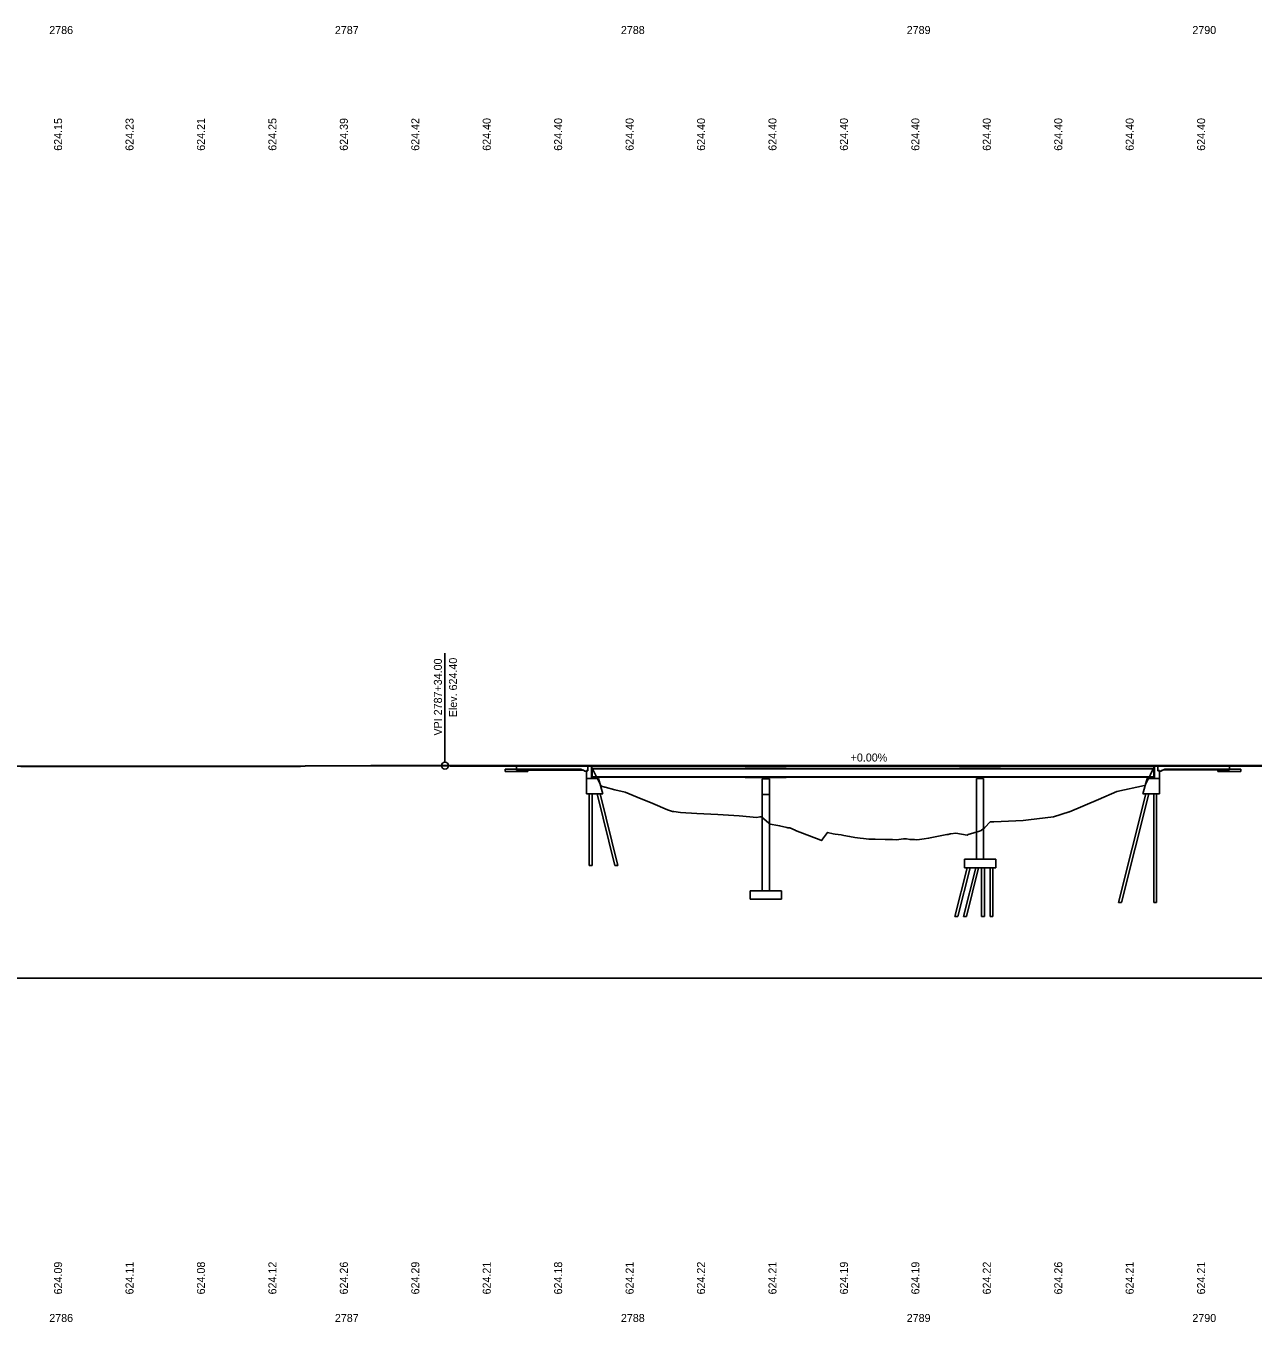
# Model space of a CAD drawing. Extents: x 2376379 to 2383101, y 559608 to 561720.
# Drawn here: x 2379153 to 2379582.4, y 559608.2 to 560061.6 of the extents above; entities that cross this region are included whole.
import ezdxf

# ---------------------------------------------------------------- set-up
doc = ezdxf.new("R2010")
doc.units = 0
for name, color, linetype in [('AP_P_Airside', 7, 'Continuous'), ('BR_X_SV_Abut', 7, 'Continuous'), ('BR_X_SV_Shot_Marker', 7, 'Continuous'), ('DR_X_Ditch', 7, 'Continuous'), ('DR_X_Erosion_Control', 7, 'Continuous'), ('DR_X_Storm_Sewer', 7, 'Continuous'), ('DR_X_Text', 7, 'Continuous'), ('DT_X_Terrain_Ground_Line', 7, 'Continuous'), ('PV_X_Driveway', 7, 'Continuous'), ('SC_Scratch1', 7, 'Continuous'), ('SV_X_Control_Cells_Found', 7, 'Continuous'), ('SV_X_Text', 7, 'Continuous'), ('UT_X_Overhead_Electric', 7, 'Continuous')]:
    doc.layers.add(name, color=color, linetype=linetype)

msp = doc.modelspace()

# ---------------------------------------------------------------- linework, layer by layer
at = {"layer": 'AP_P_Airside'}
msp.add_line((2379299.62, 559804.07), (2379299.62, 559842.15), dxfattribs=at)
msp.add_circle((2379299.62, 559802.86), 1.21, dxfattribs=at)
at = {"layer": 'BR_X_SV_Abut'}
for p, q in [((2379351.45, 559798.82), (2379351.45, 559798.57)), ((2379352.28, 559798.82), (2379351.45, 559798.82)), ((2379352.28, 559798.82), (2379352.28, 559798.57)), ((2379411.28, 559798.76), (2379411.28, 559798.55)), ((2379412.45, 559798.76), (2379411.28, 559798.76)), ((2379412.45, 559798.76), (2379412.45, 559798.55)), ((2379486.27, 559798.8), (2379486.27, 559798.67)), ((2379487.44, 559798.8), (2379486.27, 559798.8)), ((2379487.44, 559798.67), (2379486.27, 559798.67)), ((2379486.32, 559798.67), (2379486.32, 559798.38)), ((2379487.4, 559798.67), (2379487.4, 559798.38)), ((2379487.44, 559798.8), (2379487.44, 559798.67)), ((2379546.44, 559798.82), (2379546.44, 559798.57)), ((2379547.27, 559798.82), (2379546.44, 559798.82)), ((2379547.27, 559798.82), (2379547.27, 559798.57)), ((2379352.28, 559798.57), (2379351.45, 559798.57)), ((2379351.49, 559798.57), (2379351.49, 559798.34)), ((2379352.24, 559798.34), (2379351.49, 559798.34)), ((2379352.24, 559798.57), (2379352.24, 559798.34)), ((2379412.45, 559798.55), (2379411.28, 559798.55)), ((2379411.33, 559798.55), (2379411.33, 559798.26)), ((2379412.41, 559798.26), (2379411.33, 559798.26)), ((2379412.41, 559798.55), (2379412.41, 559798.26)), ((2379487.4, 559798.38), (2379486.32, 559798.38)), ((2379547.27, 559798.57), (2379546.44, 559798.57)), ((2379546.48, 559798.57), (2379546.48, 559798.34)), ((2379547.23, 559798.34), (2379546.48, 559798.34)), ((2379547.23, 559798.57), (2379547.23, 559798.34))]:
    msp.add_line(p, q, dxfattribs=at)
at = {"layer": 'DR_X_Ditch'}
for p, q in [((2379351.12, 559801.88), (2379351.12, 559798.88)), ((2379351.12, 559801.88), (2379547.62, 559801.88)), ((2379351.12, 559801.8), (2379547.62, 559801.8)), ((2379351.12, 559798.97), (2379547.62, 559798.97)), ((2379351.12, 559798.88), (2379547.62, 559798.88)), ((2379404.7, 559801.88), (2379404.7, 559801.92)), ((2379404.7, 559801.92), (2379419.03, 559801.92)), ((2379404.7, 559801.88), (2379404.7, 559801.92)), ((2379404.7, 559798.84), (2379404.7, 559798.88)), ((2379404.7, 559798.84), (2379419.03, 559798.84)), ((2379419.03, 559801.88), (2379419.03, 559801.92)), ((2379419.03, 559801.88), (2379419.03, 559801.92)), ((2379419.03, 559798.84), (2379419.03, 559798.88)), ((2379479.69, 559801.92), (2379494.02, 559801.92)), ((2379479.69, 559801.88), (2379479.69, 559801.92)), ((2379479.69, 559798.84), (2379479.69, 559798.88)), ((2379479.69, 559798.84), (2379494.02, 559798.84)), ((2379494.02, 559801.88), (2379494.02, 559801.92)), ((2379494.02, 559798.84), (2379494.02, 559798.88)), ((2379547.62, 559801.88), (2379547.62, 559798.88))]:
    msp.add_line(p, q, dxfattribs=at)
at = {"layer": 'DR_X_Storm_Sewer'}
for p, q in [((2379324.62, 559801.61), (2379324.62, 559802.86)), ((2379324.62, 559801.61), (2379347.2, 559801.61)), ((2379348.62, 559800.9), (2379347.2, 559801.61)), ((2379348.62, 559800.9), (2379349.12, 559800.9)), ((2379549.62, 559800.9), (2379550.11, 559800.9)), ((2379550.11, 559800.9), (2379551.53, 559801.61)), ((2379551.53, 559801.61), (2379574.12, 559801.61)), ((2379574.12, 559802.86), (2379574.12, 559801.61))]:
    msp.add_line(p, q, dxfattribs=at)
at = {"layer": 'DR_X_Text'}
for p, q in [((2379404.7, 559798.76), (2379404.7, 559798.8)), ((2379404.7, 559798.8), (2379419.03, 559798.8)), ((2379404.7, 559798.76), (2379419.03, 559798.76)), ((2379419.03, 559798.76), (2379419.03, 559798.8)), ((2379479.69, 559798.8), (2379479.69, 559798.84)), ((2379479.69, 559798.84), (2379494.02, 559798.84)), ((2379479.69, 559798.8), (2379494.02, 559798.8)), ((2379494.02, 559798.8), (2379494.02, 559798.84))]:
    msp.add_line(p, q, dxfattribs=at)
at = {"layer": 'DT_X_Terrain_Ground_Line'}
for p, q in [((2379320.62, 559800.86), (2379320.62, 559801.61)), ((2379324.62, 559801.61), (2379320.62, 559801.61)), ((2379320.62, 559800.86), (2379328.62, 559800.86)), ((2379328.62, 559800.86), (2379328.62, 559801.61)), ((2379570.12, 559801.61), (2379570.12, 559800.86)), ((2379570.12, 559800.86), (2379578.12, 559800.86)), ((2379574.12, 559801.61), (2379578.12, 559801.61)), ((2379578.12, 559801.61), (2379578.12, 559800.86))]:
    msp.add_line(p, q, dxfattribs=at)
at = {"layer": 'PV_X_Driveway'}
msp.add_lwpolyline([(2379151.22, 559802.54), (2379175.95, 559802.56), (2379192.51, 559802.57), (2379193.1, 559802.57), (2379198.76, 559802.57), (2379202.7, 559802.56), (2379223.33, 559802.53), (2379225.57, 559802.54), (2379247.27, 559802.61), (2379249.06, 559802.61), (2379250.63, 559802.62), (2379273.71, 559802.79), (2379297.46, 559802.74), (2379298.49, 559802.74), (2379301.44, 559802.73), (2379321.77, 559802.65), (2379322.73, 559802.64), (2379329.83, 559802.62), (2379330.86, 559802.62), (2379350.79, 559802.67), (2379354, 559796.11), (2379354.25, 559795.63), (2379354.29, 559795.64), (2379354.37, 559795.64), (2379355.61, 559795.32), (2379355.62, 559795.31), (2379359.07, 559794.38), (2379362.7, 559793.61), (2379366.85, 559791.86), (2379372.33, 559789.58), (2379377.43, 559787.42), (2379379.21, 559786.84), (2379379.32, 559786.83), (2379379.33, 559786.83), (2379379.71, 559786.77), (2379382.02, 559786.46), (2379387.77, 559786.13), (2379395.14, 559785.72), (2379402.54, 559785.34), (2379408.74, 559784.74), (2379409.78, 559784.94), (2379409.9, 559784.96), (2379410.33, 559784.93), (2379412.96, 559782.69), (2379413.38, 559782.38), (2379416.13, 559781.88), (2379416.73, 559781.81), (2379419.25, 559781.24), (2379419.58, 559781.16), (2379419.73, 559781.13), (2379420.33, 559781.07), (2379422.1, 559780.32), (2379422.23, 559780.19), (2379431.15, 559776.82), (2379431.47, 559776.63), (2379431.75, 559777.13), (2379433.44, 559779.51), (2379435.45, 559779.06), (2379436.21, 559778.94), (2379438.29, 559778.6), (2379439.21, 559778.44), (2379441.18, 559778.11), (2379443, 559777.74), (2379444.96, 559777.44), (2379446.03, 559777.34), (2379447.96, 559777.12), (2379449.07, 559777.12), (2379450.21, 559777.09), (2379453.66, 559777.02), (2379455.09, 559777.02), (2379456.23, 559777.03), (2379457.58, 559776.96), (2379460.08, 559777.23), (2379461.16, 559777.2), (2379462.36, 559776.99), (2379463.33, 559777), (2379463.95, 559776.97), (2379464.73, 559776.93), (2379465.63, 559776.99), (2379467.25, 559777.2), (2379468.86, 559777.47), (2379475.29, 559778.78), (2379475.72, 559778.82), (2379476.08, 559778.89), (2379476.4, 559778.99), (2379476.61, 559779.05), (2379478.38, 559779.19), (2379482.37, 559778.56), (2379482.75, 559778.75), (2379486.64, 559779.89), (2379487.25, 559780.18), (2379488.53, 559781.19), (2379490.34, 559783.2), (2379491.64, 559783.19), (2379501.98, 559783.71), (2379503.77, 559783.9), (2379512.59, 559784.9), (2379518.1, 559786.76), (2379518.12, 559786.76), (2379528.34, 559790.96), (2379534.7, 559793.78), (2379544.45, 559795.9), (2379544.55, 559795.93), (2379544.58, 559795.93), (2379544.61, 559795.99), (2379546.49, 559799.76), (2379547.93, 559802.66), (2379572.29, 559802.67), (2379573.41, 559802.67), (2379574.48, 559802.67), (2379598.49, 559802.67)], dxfattribs=at)
at = {"layer": 'SC_Scratch1'}
for p, q in [((2379349.12, 559798.34), (2379349.12, 559801.11)), ((2379349.12, 559801.11), (2379349.62, 559801.11)), ((2379349.62, 559801.11), (2379349.62, 559802.86)), ((2379350.87, 559798.34), (2379350.87, 559802.86)), ((2379547.87, 559798.34), (2379547.87, 559802.86)), ((2379549.12, 559801.11), (2379549.12, 559802.86)), ((2379549.12, 559801.11), (2379549.62, 559801.11)), ((2379549.62, 559798.34), (2379549.62, 559801.11)), ((2379350.87, 559798.34), (2379349.12, 559798.34)), ((2379547.87, 559798.34), (2379549.62, 559798.34))]:
    msp.add_line(p, q, dxfattribs=at)
at = {"layer": 'SV_X_Control_Cells_Found'}
for p, q in [((2379324.62, 559802.64), (2379324.62, 559801.3)), ((2379348.57, 559800.88), (2379348.12, 559801.33)), ((2379349.12, 559800.88), (2379348.57, 559800.88)), ((2379349.12, 559801.09), (2379349.12, 559792.95)), ((2379349.62, 559801.09), (2379349.12, 559801.09)), ((2379349.62, 559802.67), (2379349.62, 559801.09)), ((2379350.87, 559802.51), (2379350.87, 559798.34)), ((2379547.87, 559802.66), (2379547.87, 559798.34)), ((2379549.12, 559802.66), (2379549.12, 559801.08)), ((2379549.12, 559801.08), (2379549.62, 559801.08)), ((2379549.62, 559801.08), (2379549.62, 559792.95)), ((2379549.62, 559800.87), (2379550.12, 559800.87)), ((2379550.12, 559800.87), (2379550.58, 559801.33)), ((2379550.58, 559801.33), (2379574.12, 559801.34)), ((2379574.12, 559802.67), (2379574.12, 559801.34)), ((2379350.87, 559798.34), (2379353.37, 559798.34)), ((2379351.53, 559798.52), (2379351.53, 559798.34)), ((2379351.53, 559798.52), (2379352.2, 559798.52)), ((2379352.2, 559798.52), (2379352.2, 559798.34)), ((2379354.87, 559792.95), (2379353.37, 559798.34)), ((2379410.62, 559798.26), (2379410.62, 559759.11)), ((2379410.62, 559798.26), (2379413.12, 559798.26)), ((2379411.45, 559798.26), (2379411.45, 559798.46)), ((2379411.45, 559798.46), (2379412.28, 559798.46)), ((2379412.28, 559798.26), (2379412.28, 559798.46)), ((2379413.12, 559798.26), (2379413.12, 559759.11)), ((2379485.61, 559798.38), (2379485.61, 559770.11)), ((2379485.61, 559798.38), (2379488.11, 559798.38)), ((2379486.44, 559798.38), (2379486.44, 559798.5)), ((2379486.44, 559798.5), (2379487.27, 559798.5)), ((2379487.27, 559798.38), (2379487.27, 559798.5)), ((2379488.11, 559798.38), (2379488.11, 559770.11)), ((2379543.87, 559792.95), (2379545.37, 559798.34)), ((2379545.37, 559798.34), (2379547.87, 559798.34)), ((2379546.52, 559798.52), (2379546.52, 559798.34)), ((2379546.52, 559798.52), (2379547.19, 559798.52)), ((2379547.19, 559798.52), (2379547.19, 559798.34)), ((2379349.12, 559792.95), (2379354.87, 559792.95)), ((2379350.12, 559792.95), (2379350.12, 559767.95)), ((2379351.12, 559792.95), (2379351.12, 559767.95)), ((2379352.85, 559792.95), (2379359.1, 559767.95)), ((2379353.88, 559792.95), (2379360.13, 559767.95)), ((2379354.87, 559792.95), (2379354.87, 559792.95)), ((2379410.62, 559792.72), (2379413.12, 559792.72)), ((2379544.85, 559792.95), (2379535.35, 559754.95)), ((2379545.88, 559792.95), (2379536.38, 559754.95)), ((2379543.87, 559792.95), (2379549.62, 559792.95)), ((2379547.62, 559792.95), (2379547.62, 559754.95)), ((2379548.62, 559792.95), (2379548.62, 559754.95)), ((2379350.12, 559767.95), (2379351.12, 559767.95)), ((2379359.1, 559767.95), (2379360.13, 559767.95)), ((2379482.34, 559767.11), (2379478.09, 559750.11)), ((2379483.37, 559767.11), (2379479.12, 559750.11)), ((2379485.34, 559767.11), (2379481.09, 559750.11)), ((2379481.36, 559770.11), (2379481.36, 559767.11)), ((2379481.36, 559770.11), (2379492.36, 559770.11)), ((2379481.36, 559767.11), (2379492.36, 559767.11)), ((2379486.37, 559767.11), (2379482.12, 559750.11)), ((2379487.36, 559750.11), (2379487.36, 559767.11)), ((2379488.36, 559750.11), (2379488.36, 559767.11)), ((2379490.36, 559750.11), (2379490.36, 559767.11)), ((2379491.36, 559750.11), (2379491.36, 559767.11)), ((2379492.36, 559770.11), (2379492.36, 559767.11)), ((2379406.37, 559759.11), (2379406.37, 559756.11)), ((2379406.37, 559759.11), (2379417.37, 559759.11)), ((2379417.37, 559759.11), (2379417.37, 559756.11)), ((2379406.37, 559756.11), (2379417.37, 559756.11)), ((2379535.35, 559754.95), (2379536.38, 559754.95)), ((2379547.62, 559754.95), (2379548.62, 559754.95)), ((2379479.12, 559750.11), (2379478.09, 559750.11)), ((2379482.12, 559750.11), (2379481.09, 559750.11)), ((2379487.36, 559750.11), (2379488.36, 559750.11)), ((2379490.36, 559750.11), (2379491.36, 559750.11))]:
    msp.add_line(p, q, dxfattribs=at)
for points in [[(2379348.12, 559801.33), (2379330.86, 559801.29), (2379329.83, 559801.29), (2379324.62, 559801.3)], [(2379350.79, 559802.67), (2379355.61, 559802.67), (2379375.64, 559802.68), (2379376.26, 559802.68), (2379402.22, 559802.68), (2379403.42, 559802.68), (2379409.78, 559802.68), (2379427.31, 559802.67), (2379427.89, 559802.67), (2379456.09, 559802.64), (2379456.23, 559802.64), (2379456.39, 559802.64), (2379463.95, 559802.65), (2379488.71, 559802.68), (2379489.96, 559802.68), (2379503.75, 559802.7), (2379509.27, 559802.71), (2379514.92, 559802.72), (2379515.19, 559802.72), (2379515.21, 559802.72), (2379515.67, 559802.72), (2379518.12, 559802.72), (2379530.19, 559802.7), (2379530.91, 559802.7), (2379543.21, 559802.67), (2379547.83, 559802.66), (2379547.93, 559802.66)]]:
    msp.add_lwpolyline(points, dxfattribs=at)
at = {"layer": 'SV_X_Text'}
msp.add_line((2378765.62, 559728.46), (2380329.61, 559728.46), dxfattribs=at)
at = {"layer": 'UT_X_Overhead_Electric'}
msp.add_line((2379299.62, 559802.86), (2379590.62, 559802.86), dxfattribs=at)
for points in [[(2379193.12, 559802.69), (2379175.95, 559802.69), (2379151.22, 559802.67), (2379147.75, 559802.66), (2379138.93, 559802.68), (2379124.24, 559802.71), (2379099.25, 559802.76), (2379084.76, 559802.78), (2379075.73, 559802.79), (2379048.26, 559802.74), (2379046.54, 559802.74), (2379043.12, 559802.73)], [(2379193.12, 559802.69), (2379203.29, 559802.69), (2379223.33, 559802.66), (2379225.57, 559802.66), (2379240.62, 559802.71)], [(2379240.62, 559802.71), (2379247.27, 559802.73), (2379250.63, 559802.74), (2379273.71, 559802.91), (2379297.46, 559802.87), (2379298.49, 559802.87), (2379299.62, 559802.86)]]:
    msp.add_lwpolyline(points, dxfattribs=at)

# ---------------------------------------------------------------- texts
at = {"layer": 'AP_P_Airside'}
for s, p in [('VPI 2787+34.00', (2379298.53, 559813.39)), ('Elev. 624.40', (2379303.82, 559819.8))]:
    msp.add_text(s, height=2.8, rotation=90, dxfattribs=at).set_placement(p)
msp.add_text('+0.00%', height=2.8, dxfattribs=at).set_placement((2379441.57, 559804.3))
at = {"layer": 'BR_X_SV_Shot_Marker'}
for s, p in [('2786', (2379161.14, 560058.78)), ('2787', (2379261.09, 560058.78)), ('2788', (2379361.18, 560058.78)), ('2789', (2379461.2, 560058.78)), ('2790', (2379561.16, 560058.78)), ('2786', (2379161.14, 559608.25)), ('2787', (2379261.09, 559608.25)), ('2788', (2379361.18, 559608.25)), ('2789', (2379461.2, 559608.25)), ('2790', (2379561.16, 559608.25))]:
    msp.add_text(s, height=2.8, dxfattribs=at).set_placement(p)
for s, p in [('624.09', (2379165.62, 559617.89)), ('624.11', (2379190.62, 559617.89)), ('624.08', (2379215.62, 559617.89)), ('624.12', (2379240.62, 559617.89)), ('624.26', (2379265.62, 559617.89)), ('624.29', (2379290.62, 559617.89)), ('624.21', (2379315.62, 559617.89)), ('624.18', (2379340.62, 559617.89)), ('624.21', (2379365.62, 559617.89)), ('624.22', (2379390.62, 559617.89)), ('624.21', (2379415.62, 559617.89)), ('624.19', (2379440.62, 559617.89)), ('624.19', (2379465.62, 559617.89)), ('624.22', (2379490.62, 559617.89)), ('624.26', (2379515.62, 559617.89)), ('624.21', (2379540.62, 559617.89)), ('624.21', (2379565.62, 559617.89))]:
    msp.add_text(s, height=2.8, rotation=90, dxfattribs=at).set_placement(p)
at = {"layer": 'DR_X_Erosion_Control'}
for s, p in [('624.15', (2379165.62, 560017.95)), ('624.23', (2379190.62, 560017.95)), ('624.21', (2379215.62, 560017.95)), ('624.25', (2379240.62, 560017.95)), ('624.39', (2379265.62, 560017.95)), ('624.42', (2379290.62, 560017.95)), ('624.40', (2379315.62, 560017.95)), ('624.40', (2379340.62, 560017.95)), ('624.40', (2379365.62, 560017.95)), ('624.40', (2379390.62, 560017.95)), ('624.40', (2379415.62, 560017.95)), ('624.40', (2379440.62, 560017.95)), ('624.40', (2379465.62, 560017.95)), ('624.40', (2379490.62, 560017.95)), ('624.40', (2379515.62, 560017.95)), ('624.40', (2379540.62, 560017.95)), ('624.40', (2379565.62, 560017.95))]:
    msp.add_text(s, height=2.8, rotation=90, dxfattribs=at).set_placement(p)

doc.saveas('drawing.dxf')
